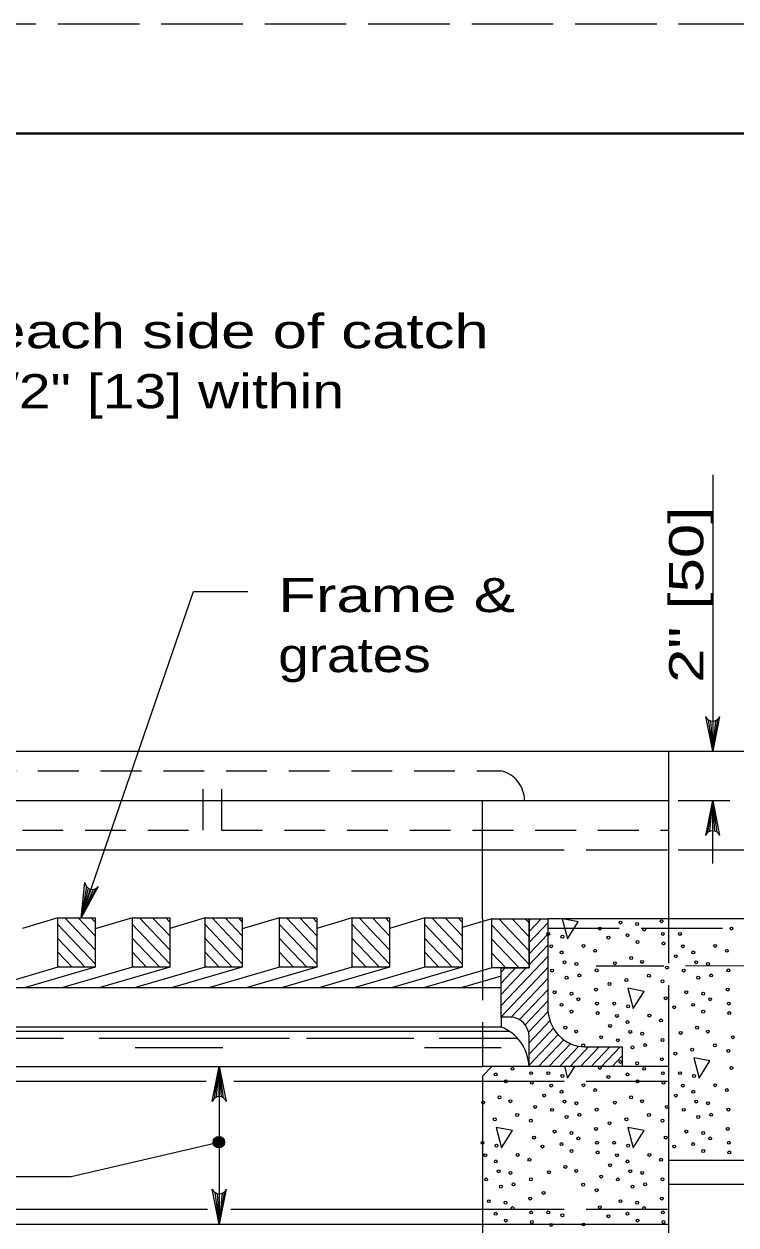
# Model space of a CAD drawing. Extents: x 1352.5 to 1386.5, y 735.9 to 779.9.
# Drawn here: x 1364.27 to 1367.52, y 774.44 to 779.92 of the extents above; entities that cross this region are included whole.
import ezdxf

# ---------------------------------------------------------------- set-up
doc = ezdxf.new("R2010")
doc.units = 0
doc.header["$LTSCALE"] = 0.062
doc.linetypes.add('LONG_DASHED', pattern=[7.5, 6, -1.5])
doc.linetypes.add('MEDIUM_DASHED', pattern=[4.5, 3, -1.5])
doc.layers.add('1', color=7, linetype='Continuous', lineweight=13)

msp = doc.modelspace()

# ---------------------------------------------------------------- hatches: boundary and pattern name
at = {"layer": '1'}
msp.add_hatch(color=256, dxfattribs=at).paths.add_polyline_path([(1365.18985, 774.81443, 1), (1365.13703, 774.81443, 1)])

# ---------------------------------------------------------------- linework, layer by layer
at = {"layer": '1', "lineweight": 25}
for p, q in [((1354.513, 779.41967), (1386.013, 779.41967)), ((1356.99975, 776.599), (1369.78625, 776.599)), ((1367.21625, 775.83442), (1367.21625, 776.599)), ((1359.56983, 776.37417), (1367.21625, 776.37417)), ((1366.36658, 775.83442), (1366.36658, 776.37417)), ((1360.41942, 776.14925), (1366.36658, 776.14925)), ((1364.4295, 775.838), (1364.26808, 775.7905)), ((1364.4295, 775.838), (1364.59942, 775.838)), ((1364.76933, 775.838), (1364.59942, 775.78808)), ((1365.10075, 775.838), (1364.93925, 775.7905)), ((1365.44058, 775.838), (1365.27067, 775.78808)), ((1365.77192, 775.838), (1365.6105, 775.7905)), ((1366.10325, 775.838), (1365.94183, 775.7905)), ((1366.40908, 775.83442), (1366.27317, 775.7945)), ((1368.40567, 775.83442), (1366.664, 775.83442)), ((1363.57175, 775.51967), (1366.45158, 775.51967)), ((1366.49408, 775.38475), (1366.45158, 775.38475)), ((1366.45158, 775.38475), (1366.45158, 775.33975)), ((1366.45158, 775.33975), (1363.58858, 775.33975)), ((1363.60542, 775.15983), (1366.36658, 775.15983)), ((1366.40908, 775.15983), (1366.36658, 775.15983)), ((1367.21625, 775.15983), (1367.00383, 775.15983)), ((1367.21625, 774.73258), (1367.21625, 775.15983)), ((1360.41942, 775.09242), (1365.10567, 775.09242)), ((1368.40567, 774.62017), (1367.21625, 774.62017)), ((1360.41942, 774.50775), (1365.11233, 774.50775)), ((1365.2185, 774.50775), (1366.36658, 774.50775)), ((1359.56983, 774.44025), (1367.21625, 774.44025))]:
    msp.add_line(p, q, dxfattribs=at)
at = {"layer": '1'}
for p, q in [((1367.4165, 777.86067), (1367.4165, 776.599)), ((1367.39633, 776.74325), (1367.4165, 776.599)), ((1367.40625, 776.73833), (1367.4165, 776.599)), ((1367.43875, 776.74492), (1367.4165, 776.599)), ((1367.42942, 776.73942), (1367.4165, 776.599)), ((1367.4165, 776.73683), (1367.4165, 776.599)), ((1367.25867, 776.37417), (1367.49517, 776.37417)), ((1367.39417, 776.22825), (1367.4165, 776.37417)), ((1367.4035, 776.23375), (1367.4165, 776.37417)), ((1367.4165, 776.08667), (1367.4165, 776.37417)), ((1367.4165, 776.23633), (1367.4165, 776.37417)), ((1367.42667, 776.23483), (1367.4165, 776.37417)), ((1367.43667, 776.22992), (1367.4165, 776.37417)), ((1364.55917, 775.98167), (1364.53617, 775.83792)), ((1364.56733, 775.97408), (1364.53617, 775.83792)), ((1364.60033, 775.97083), (1364.53617, 775.83792)), ((1364.57667, 775.96967), (1364.53617, 775.83792)), ((1364.58975, 775.96833), (1364.53617, 775.83792)), ((1364.46167, 775.838), (1364.59942, 775.69208)), ((1364.52175, 775.838), (1364.59942, 775.75567)), ((1364.58183, 775.838), (1364.59942, 775.81933)), ((1364.8015, 775.838), (1364.93925, 775.69208)), ((1364.86158, 775.838), (1364.93925, 775.75567)), ((1364.92167, 775.838), (1364.93925, 775.81933)), ((1365.13283, 775.838), (1365.27067, 775.69208)), ((1365.193, 775.838), (1365.27067, 775.75567)), ((1365.253, 775.838), (1365.27067, 775.81933)), ((1365.47267, 775.838), (1365.6105, 775.69208)), ((1365.53283, 775.838), (1365.6105, 775.75567)), ((1365.59283, 775.838), (1365.6105, 775.81933)), ((1365.804, 775.838), (1365.94183, 775.69208)), ((1365.86417, 775.838), (1365.94183, 775.75567)), ((1365.92417, 775.838), (1365.94183, 775.81933)), ((1366.13542, 775.838), (1366.27317, 775.69208)), ((1366.1955, 775.838), (1366.27317, 775.75567)), ((1366.2555, 775.838), (1366.27317, 775.81933)), ((1366.44125, 775.83442), (1366.579, 775.68858)), ((1366.50133, 775.83442), (1366.579, 775.75217)), ((1366.56142, 775.83442), (1366.579, 775.81575)), ((1366.579, 775.77625), (1366.63392, 775.83442)), ((1366.579, 775.82708), (1366.58592, 775.83442)), ((1366.664, 775.83442), (1366.664, 775.42967)), ((1366.664, 775.83442), (1366.664, 775.42967)), ((1366.8035, 775.82092), (1366.73358, 775.83442)), ((1364.4295, 775.80833), (1364.59942, 775.6285)), ((1364.76933, 775.80833), (1364.93925, 775.6285)), ((1365.10075, 775.80833), (1365.27067, 775.6285)), ((1365.44058, 775.80833), (1365.6105, 775.6285)), ((1365.77192, 775.80833), (1365.94183, 775.6285)), ((1366.10325, 775.80833), (1366.27317, 775.6285)), ((1366.40908, 775.80483), (1366.579, 775.62492)), ((1366.579, 775.72542), (1366.664, 775.81533)), ((1366.579, 775.6745), (1366.664, 775.76442)), ((1364.4295, 775.74483), (1364.55383, 775.61308)), ((1364.76933, 775.74483), (1364.89367, 775.61308)), ((1365.10075, 775.74483), (1365.225, 775.61308)), ((1365.44058, 775.74483), (1365.56492, 775.61308)), ((1365.77192, 775.74483), (1365.89625, 775.61308)), ((1366.10325, 775.74483), (1366.22758, 775.61308)), ((1366.40908, 775.74125), (1366.53342, 775.60958)), ((1366.579, 775.62358), (1366.664, 775.71358)), ((1364.4295, 775.68117), (1364.49383, 775.61308)), ((1364.76933, 775.68117), (1364.83367, 775.61308)), ((1365.10075, 775.68117), (1365.165, 775.61308)), ((1365.44058, 775.68117), (1365.50483, 775.61308)), ((1365.77192, 775.68117), (1365.83617, 775.61308)), ((1366.10325, 775.68117), (1366.1675, 775.61308)), ((1366.40908, 775.67767), (1366.47342, 775.60958)), ((1366.45158, 775.43783), (1366.664, 775.66267)), ((1364.4295, 775.61308), (1364.11167, 775.51967)), ((1364.59942, 775.61308), (1364.28167, 775.51967)), ((1364.4295, 775.61758), (1364.43367, 775.61308)), ((1364.76933, 775.61308), (1364.4515, 775.51967)), ((1364.93925, 775.61308), (1364.6215, 775.51967)), ((1364.76933, 775.61758), (1364.77358, 775.61308)), ((1365.10075, 775.61308), (1364.78283, 775.51967)), ((1365.27067, 775.61308), (1364.95283, 775.51967)), ((1365.10075, 775.61758), (1365.10492, 775.61308)), ((1365.44058, 775.61308), (1365.12267, 775.51967)), ((1365.6105, 775.61308), (1365.29267, 775.51967)), ((1365.44058, 775.61758), (1365.44475, 775.61308)), ((1365.77192, 775.61308), (1365.454, 775.51967)), ((1365.94183, 775.61308), (1365.624, 775.51967)), ((1365.77192, 775.61758), (1365.77608, 775.61308)), ((1366.10325, 775.61308), (1365.78533, 775.51967)), ((1366.27317, 775.61308), (1365.95533, 775.51967)), ((1366.40908, 775.60958), (1366.10317, 775.51967)), ((1366.10325, 775.61758), (1366.10742, 775.61308)), ((1366.40908, 775.61408), (1366.41325, 775.60958)), ((1366.45158, 775.38692), (1366.664, 775.61175)), ((1366.45158, 775.48875), (1366.56575, 775.60958)), ((1366.45158, 775.53958), (1366.51767, 775.60958)), ((1366.45158, 775.5905), (1366.46967, 775.60958)), ((1366.45158, 775.57208), (1366.27317, 775.51967)), ((1366.49742, 775.38467), (1366.66408, 775.56092)), ((1366.53508, 775.37358), (1366.66408, 775.51008)), ((1366.561, 775.35017), (1366.66408, 775.45925)), ((1366.57667, 775.31583), (1366.665, 775.40942)), ((1366.579, 775.26742), (1366.67425, 775.36825)), ((1366.579, 775.21658), (1366.69, 775.334)), ((1366.4895, 775.32017), (1363.59042, 775.32017)), ((1364.4555, 775.28767), (1363.59342, 775.28767)), ((1365.48533, 775.28767), (1364.61708, 775.28767)), ((1366.0535, 775.28767), (1365.56317, 775.28767)), ((1366.52692, 775.28767), (1366.16883, 775.28767)), ((1366.579, 775.16567), (1366.71108, 775.3055)), ((1366.62158, 775.15983), (1366.737, 775.282)), ((1365.18242, 775.24425), (1364.7815, 775.24425)), ((1366.45158, 775.24425), (1366.1025, 775.24425)), ((1366.66967, 775.15983), (1366.768, 775.26392)), ((1366.71775, 775.15983), (1366.80525, 775.2525)), ((1366.76575, 775.15983), (1366.85067, 775.24975)), ((1366.81375, 775.15983), (1366.89875, 775.24975)), ((1366.86183, 775.15983), (1366.94683, 775.24975)), ((1366.90992, 775.15983), (1366.99492, 775.24975)), ((1365.14308, 775.01392), (1365.16542, 775.15983)), ((1365.1525, 775.01942), (1365.16542, 775.15983)), ((1365.16542, 775.15983), (1365.16542, 774.44025)), ((1365.16542, 775.022), (1365.16542, 775.15983)), ((1365.17558, 775.0205), (1365.16542, 775.15983)), ((1365.18558, 775.01558), (1365.16542, 775.15983)), ((1366.958, 775.15983), (1367.00383, 775.20833)), ((1365.23183, 775.09242), (1366.36658, 775.09242)), ((1365.14525, 774.5845), (1365.16542, 774.44025)), ((1365.15525, 774.57958), (1365.16542, 774.44025)), ((1365.18775, 774.58617), (1365.16542, 774.44025)), ((1365.17842, 774.58067), (1365.16542, 774.44025)), ((1365.16542, 774.57808), (1365.16542, 774.44025))]:
    msp.add_line(p, q, dxfattribs=at)
at = {"layer": '1', "linetype": 'MEDIUM_DASHED'}
for p, q in [((1360.33442, 776.50908), (1366.45158, 776.50908)), ((1365.09225, 776.23925), (1365.09225, 776.50908)), ((1365.17717, 776.23925), (1365.17717, 776.50908)), ((1361.69383, 776.23925), (1365.09225, 776.23925)), ((1365.17717, 776.23925), (1367.21625, 776.23925))]:
    msp.add_line(p, q, dxfattribs=at)
at = {"layer": '1', "linetype": 'LONG_DASHED', "lineweight": 25}
for p, q in [((1366.36658, 776.14925), (1367.21625, 776.14925)), ((1366.36658, 775.83442), (1366.36658, 775.15983)), ((1367.21625, 775.15983), (1367.21625, 775.83442)), ((1366.36658, 775.09242), (1367.21625, 775.09242)), ((1366.36658, 774.50775), (1367.21625, 774.50775))]:
    msp.add_line(p, q, dxfattribs=at)
at = {"layer": '1', "linetype": 'LONG_DASHED'}
for p, q in [((1368.40567, 775.7895), (1366.664, 775.7895)), ((1368.13708, 775.61933), (1366.88525, 775.61817))]:
    msp.add_line(p, q, dxfattribs=at)
msp.add_lwpolyline([(1352.513, 757.91967), (1386.513, 757.91967), (1386.513, 779.91967), (1352.513, 779.91967)], close=True, dxfattribs=at)
at = {"layer": '1', "lineweight": 40}
msp.add_lwpolyline([(1354.513, 779.41967), (1386.013, 779.41967), (1386.013, 758.41967), (1354.513, 758.41967)], close=True, dxfattribs=at)
msp.add_lwpolyline([(1354.513, 779.41967), (1386.013, 779.41967), (1386.013, 758.41967), (1354.513, 758.41967)], close=True, dxfattribs=at)
at = {"layer": '1'}
for points in [[(1364.53617, 775.83792), (1365.04833, 777.32792), (1365.2965, 777.32792)], [(1367.44833, 776.75833), (1367.4165, 776.599), (1367.38458, 776.75833)], [(1367.38458, 776.21483), (1367.4165, 776.37417), (1367.44833, 776.21483)], [(1367.25867, 776.14925), (1367.61683, 776.14925), (1367.80467, 776.14925)], [(1364.61342, 775.98083), (1364.53617, 775.83792), (1364.5525, 775.9995)], [(1366.72992, 775.83442), (1366.754, 775.74308), (1366.8035, 775.82092)], [(1366.83392, 775.24975), (1367.00383, 775.24975), (1367.00383, 775.15983), (1366.579, 775.15983)], [(1366.83392, 775.24975), (1367.00383, 775.24975), (1367.00383, 775.15983), (1366.579, 775.15983)], [(1365.13358, 775.0005), (1365.16542, 775.15983), (1365.19725, 775.0005)], [(1366.74008, 775.15983), (1366.754, 775.107), (1366.78758, 775.15983)], [(1364.20317, 774.65708), (1364.49008, 774.65708), (1365.16342, 774.81442)], [(1365.19725, 774.59958), (1365.16542, 774.44025), (1365.13358, 774.59958)]]:
    msp.add_lwpolyline(points, dxfattribs=at)
at = {"layer": '1', "lineweight": 25}
for points in [[(1364.4295, 775.61308), (1364.4295, 775.838), (1364.59942, 775.838), (1364.59942, 775.61308)], [(1364.76933, 775.61308), (1364.76933, 775.838), (1364.93925, 775.838), (1364.93925, 775.61308)], [(1365.10075, 775.61308), (1365.10075, 775.838), (1365.27067, 775.838), (1365.27067, 775.61308)], [(1365.44058, 775.61308), (1365.44058, 775.838), (1365.6105, 775.838), (1365.6105, 775.61308)], [(1365.77192, 775.61308), (1365.77192, 775.838), (1365.94183, 775.838), (1365.94183, 775.61308)], [(1366.10325, 775.61308), (1366.10325, 775.838), (1366.27317, 775.838), (1366.27317, 775.61308)], [(1366.40908, 775.60958), (1366.40908, 775.83442), (1366.579, 775.83442), (1366.579, 775.60958)]]:
    msp.add_lwpolyline(points, close=True, dxfattribs=at)
for points in [[(1366.45158, 775.38475), (1366.45158, 775.60958), (1366.579, 775.60958), (1366.579, 775.83442), (1366.664, 775.83442), (1366.664, 775.42967)], [(1366.83392, 775.24975), (1367.00383, 775.24975), (1367.00383, 775.15983), (1366.579, 775.15983), (1366.579, 775.29475)], [(1366.579, 775.15983), (1366.40908, 775.15983), (1366.36658, 775.11483), (1366.36658, 771.33708)], [(1358.38042, 774.73258), (1359.56983, 774.73258), (1359.56983, 770.66242), (1367.21625, 770.66242), (1367.21625, 774.73258), (1368.40567, 774.73258), (1369.78625, 774.73258)]]:
    msp.add_lwpolyline(points, dxfattribs=at)
at = {"layer": '1'}
for points in [[(1367.03017, 775.51725), (1367.05442, 775.425), (1367.10392, 775.50283)], [(1367.33058, 775.19917), (1367.35483, 775.107), (1367.40425, 775.18483)], [(1366.42942, 774.88117), (1366.45367, 774.789), (1366.50308, 774.86683)], [(1367.03017, 774.88117), (1367.05442, 774.789), (1367.10392, 774.86683)]]:
    msp.add_lwpolyline(points, close=True, dxfattribs=at)
for radius in [0.02641, 0.0177]:
    msp.add_circle((1365.16344, 774.81443), radius, dxfattribs=at)
for centre, start, end in [((1367.41644, 776.77117), 202.08782, 337.91395), ((1367.41651, 776.20197), 22.08782, 157.91395), ((1364.58667, 776.00248), 185.01307, 320.8392), ((1365.16546, 774.98767), 22.08782, 157.91395), ((1365.16539, 774.61241), 202.08782, 337.91395)]:
    msp.add_arc(centre, 0.03438, start, end, dxfattribs=at)
at = {"layer": '1', "linetype": 'MEDIUM_DASHED'}
msp.add_ellipse((1366.42435, 776.37001), major_axis=(0, 0.142), ratio=0.944544, start_param=4.7414242, end_param=6.0787758, dxfattribs=at)
at = {"layer": '1'}
for centre in [(1366.99586, 775.81688), (1367.18305, 775.82306), (1366.6666, 775.76531), (1366.90179, 775.78938), (1367.0275, 775.75932), (1367.07241, 775.81026), (1367.1043, 775.78508), (1367.18946, 775.76531), (1367.26735, 775.76531), (1367.50255, 775.78938), (1366.67956, 775.70865), (1366.73063, 775.75243), (1366.82715, 775.71035), (1366.94074, 775.74814), (1367.07321, 775.7281), (1367.19186, 775.72153), (1367.28032, 775.70865), (1367.42791, 775.71035), (1366.72737, 775.6803), (1366.88067, 775.68803), (1367.04482, 775.65512), (1367.24863, 775.66312), (1367.32813, 775.6803), (1367.48142, 775.68803), (1366.68357, 775.59788), (1366.74039, 775.63567), (1366.79471, 775.62788), (1366.88717, 775.59867), (1366.97018, 775.63111), (1367.09429, 775.6371), (1367.20783, 775.61134), (1367.28433, 775.59788), (1367.34115, 775.63567), (1367.39547, 775.62788), (1367.48793, 775.59867), (1366.75005, 775.56523), (1366.80847, 775.57556), (1367.0229, 775.55463), (1367.12588, 775.5744), (1367.18755, 775.54864), (1367.35081, 775.56523), (1367.40923, 775.57556), (1366.69548, 775.49887), (1366.77203, 775.49224), (1366.88422, 775.51085), (1366.9458, 775.53661), (1367.29624, 775.49887), (1367.37279, 775.49224), (1367.48498, 775.51085), (1366.72712, 775.44131), (1366.80392, 775.46707), (1366.88908, 775.4473), (1366.96697, 775.4473), (1367.03101, 775.43442), (1367.20217, 775.47136), (1367.24112, 775.43012), (1367.32788, 775.44131), (1367.40468, 775.46707), (1367.48983, 775.4473), (1366.77283, 775.41009), (1366.89148, 775.40352), (1366.97994, 775.39064), (1367.12753, 775.39233), (1367.37359, 775.41009), (1367.49224, 775.40352), (1366.74444, 775.33711), (1366.79391, 775.31908), (1366.94825, 775.34511), (1367.02775, 775.36228), (1367.04077, 775.31765), (1367.18104, 775.37002), (1367.3452, 775.33711), (1367.39466, 775.31908), (1366.90745, 775.29333), (1366.98395, 775.27986), (1367.09509, 775.30986), (1367.18755, 775.28066), (1367.27056, 775.3131), (1367.50821, 775.29333), (1366.8255, 775.25638), (1367.05043, 775.24721), (1367.10885, 775.25755), (1367.24618, 775.21859), (1367.32327, 775.23661), (1367.42625, 775.25638), (1367.48793, 775.23062), (1366.90179, 775.15335), (1366.99586, 775.18085), (1367.07241, 775.17423), (1367.1846, 775.19283), (1367.50255, 775.15335), (1366.42674, 775.12329), (1366.50354, 775.14905), (1366.5887, 775.12928), (1366.6666, 775.12928), (1366.73063, 775.1164), (1366.94074, 775.11211), (1367.0275, 775.12329), (1367.1043, 775.14905), (1367.18946, 775.12928), (1367.26735, 775.12928), (1367.33138, 775.1164), (1366.47245, 775.09208), (1366.5911, 775.0855), (1366.67956, 775.07262), (1366.72737, 775.04427), (1366.82715, 775.07432), (1366.88067, 775.05201), (1367.07321, 775.09208), (1367.19186, 775.0855), (1367.28032, 775.07262), (1367.32813, 775.04427), (1367.42791, 775.07432), (1367.48142, 775.05201), (1366.36942, 774.99508), (1366.44407, 775.01909), (1366.49353, 775.00107), (1366.64787, 775.02709), (1366.74039, 774.99964), (1366.79471, 774.99185), (1366.97018, 774.99508), (1367.04482, 775.01909), (1367.09429, 775.00107), (1367.24863, 775.02709), (1367.34115, 774.99964), (1367.39547, 774.99185), (1366.52512, 774.93837), (1366.60707, 774.97531), (1366.68357, 774.96185), (1366.80847, 774.93953), (1366.88717, 774.96264), (1367.12588, 774.93837), (1367.20783, 774.97531), (1367.28433, 774.96185), (1367.40923, 774.93953), (1367.48793, 774.96264), (1366.42214, 774.9186), (1366.5868, 774.91261), (1366.75005, 774.9292), (1366.9458, 774.90058), (1367.0229, 774.9186), (1367.18755, 774.91261), (1367.35081, 774.9292), (1366.60141, 774.83533), (1366.69548, 774.86284), (1366.77203, 774.85621), (1366.80392, 774.83104), (1366.88422, 774.87482), (1367.20217, 774.83533), (1367.29624, 774.86284), (1367.37279, 774.85621), (1367.40468, 774.83104), (1367.48498, 774.87482), (1366.36622, 774.81127), (1366.43025, 774.79839), (1366.64036, 774.7941), (1366.72712, 774.80528), (1366.77283, 774.77406), (1366.88908, 774.81127), (1366.96697, 774.81127), (1367.03101, 774.79839), (1367.24112, 774.7941), (1367.32788, 774.80528), (1367.37359, 774.77406), (1367.48983, 774.81127), (1366.37918, 774.75461), (1366.42699, 774.72625), (1366.52677, 774.7563), (1366.58029, 774.73399), (1366.89148, 774.76749), (1366.97994, 774.75461), (1367.02775, 774.72625), (1367.12753, 774.7563), (1367.18104, 774.73399), (1367.49224, 774.76749), (1366.44001, 774.68162), (1366.49433, 774.67383), (1366.6698, 774.67707), (1366.74444, 774.70108), (1366.79391, 774.68305), (1366.94825, 774.70908), (1367.04077, 774.68162), (1367.09509, 774.67383), (1366.38319, 774.64383), (1366.44967, 774.61118), (1366.5081, 774.62152), (1366.5868, 774.64463), (1366.8255, 774.62035), (1366.90745, 774.6573), (1366.98395, 774.64383), (1367.05043, 774.61118), (1367.10885, 774.62152), (1367.18755, 774.64463), (1366.58384, 774.5568), (1366.64542, 774.58256), (1366.88717, 774.59459), (1367.1846, 774.5568), (1366.3951, 774.54482), (1366.47165, 774.5382), (1366.50354, 774.51302), (1366.90179, 774.51732), (1366.99586, 774.54482), (1367.07241, 774.5382), (1367.1043, 774.51302), (1366.42674, 774.48726), (1366.47245, 774.45605), (1366.5887, 774.49325), (1366.5911, 774.44947), (1366.6666, 774.49325), (1366.73063, 774.48037), (1366.94074, 774.47608), (1367.0275, 774.48726), (1367.07321, 774.45605), (1367.18946, 774.49325), (1367.19186, 774.44947), (1366.67956, 774.43659), (1366.82715, 774.43829)]:
    msp.add_ellipse(centre, major_axis=(0, 0.0068), ratio=0.944544, dxfattribs=at)
at = {"layer": '1', "lineweight": 25}
for centre, major_axis, start_param, end_param in [((1366.49406, 775.29476), (0, 0.08995), 4.712389, 6.2831853), ((1366.8339, 775.42968), (0, 0.1799), 1.5707963, 3.1415927), ((1366.38685, 775.14779), (0, 0.2038), 4.7715086, 5.9402716)]:
    msp.add_ellipse(centre, major_axis=major_axis, ratio=0.944544, start_param=start_param, end_param=end_param, dxfattribs=at)
at = {"layer": '1'}
msp.add_ellipse((1366.8339, 775.42968), major_axis=(0, 0.1799), ratio=0.944544, start_param=1.5707963, end_param=3.1415927, dxfattribs=at)
msp.add_ellipse((1366.8339, 775.42968), major_axis=(0, 0.1799), ratio=0.944544, start_param=1.5707963, end_param=3.1415927, dxfattribs=at)

# ---------------------------------------------------------------- texts
for s, width, p in [('Drop gutter 2" in 20\' [50 in 6 m] from each side of catch', 1.35, (1359.52592, 778.43933)), ('basin for normal transverse slope, and 1/2" [13] within', 1.25, (1359.52592, 778.16533)), ('Frame &', 1.35, (1365.43442, 777.2345)), ('grates', 1.2, (1365.43442, 776.9605))]:
    msp.add_text(s, height=0.156, dxfattribs=dict(at, width=width)).set_placement(p)
at = {"layer": '1', "width": 1.35}
msp.add_text('2" [50]', height=0.156, rotation=90, dxfattribs=at).set_placement((1367.37383, 776.91133))

doc.saveas('drawing.dxf')
